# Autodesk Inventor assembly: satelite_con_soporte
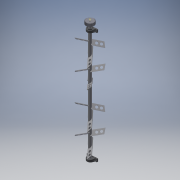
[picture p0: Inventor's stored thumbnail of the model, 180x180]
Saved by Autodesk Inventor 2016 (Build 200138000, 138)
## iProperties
Created: 2016-10
Part Number: satelite_con_soporte
Document SubType Name: Assembly
Designer: Ingenieria
Author: Ingenieria
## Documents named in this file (3)
- C:\Users\ingenieria\Desktop\Project\satelite_con_soporte.iam
- C:\Users\ingenieria\Desktop\Project\Montaje_satelites.iam
- C:\Users\ingenieria\Desktop\Project\SY 55 FM.iam
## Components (3 placed, 2 different names)
1. Montaje_satelites:1 [sub-assembly] — Mate:1, Mate:2, Mate:5, Mate:7
2. SY 55 FM:1 [sub-assembly] — Mate:3, Angle:1, Mate:5
3. SY 55 FM:2 [sub-assembly] — Mate:4, Mate:6, Mate:7
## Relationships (8: Mate 7, Angle 1)
- Mate:1: Montaje_satelites:1
- Mate:2: Montaje_satelites:1
- Mate:3: SY 55 FM:1
- Mate:4: SY 55 FM:2
- Angle:1: SY 55 FM:1
- Mate:5: Montaje_satelites:1 ↔ SY 55 FM:1
- Mate:6: SY 55 FM:2
- Mate:7: Montaje_satelites:1 ↔ SY 55 FM:2
